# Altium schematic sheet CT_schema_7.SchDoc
size 274 x 160 mm
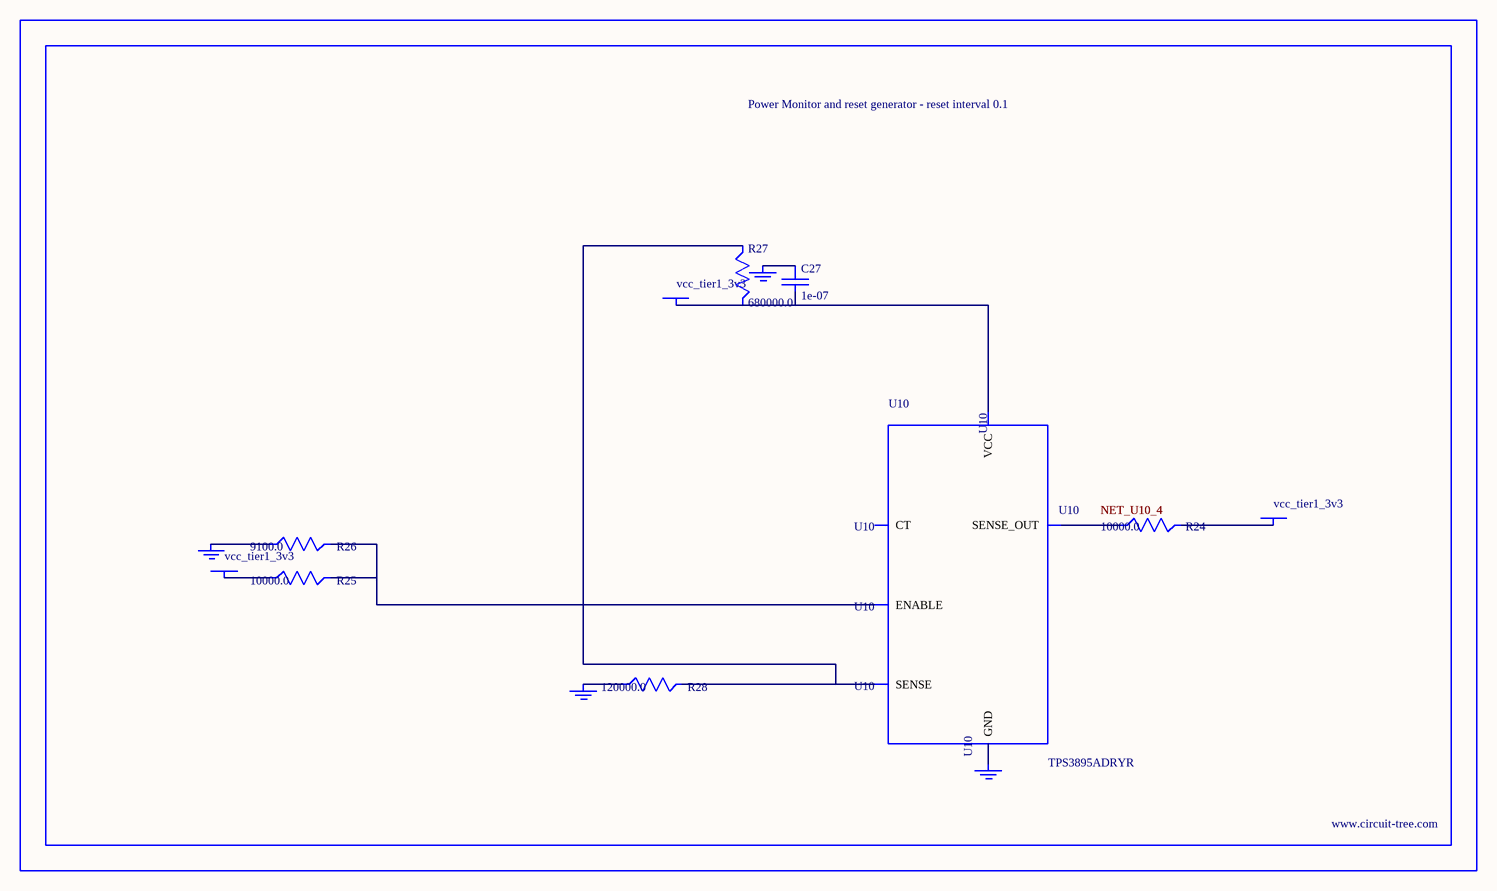
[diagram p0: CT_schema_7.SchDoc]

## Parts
BORDER6  (no value)
C27  1e-07  [C0402]
GND_INSTANCE_6_0  (no value)
GND_INSTANCE_6_1  (no value)
GND_INSTANCE_6_2  (no value)
GND_INSTANCE_6_3  (no value)
POWER_INSTANCE_6_0  vcc_tier1_3v3
POWER_INSTANCE_6_1  vcc_tier1_3v3
POWER_INSTANCE_6_2  vcc_tier1_3v3
R24  10000.0  [R0603]
R25  10000.0  [R0603]
R26  9100.0  [R0603]
R27  680000.0  [R0603]
R28  120000.0  [R0603]
U10  TPS3895ADRYR  [SON-6]

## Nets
NetC27_1: C27.1 GND_INSTANCE_6_2.0(GND)
NetC27_2: C27.2 POWER_INSTANCE_6_2.0(PWR) R27.2 U10.6(VCC)
NetGND_INSTANCE_6_0_0: GND_INSTANCE_6_0.0(GND) R26.1
NetGND_INSTANCE_6_1_0: GND_INSTANCE_6_1.0(GND) R28.1
NetGND_INSTANCE_6_3_0: GND_INSTANCE_6_3.0(GND) U10.2(GND)
NetPOWER_INSTANCE_6_0_0: POWER_INSTANCE_6_0.0(PWR) R25.1
NetPOWER_INSTANCE_6_1_0: POWER_INSTANCE_6_1.0(PWR) R24.2
NetR24_1: R24.1 U10.4(SENSE_OUT)
NetR25_2: R25.2 R26.2 U10.1(ENABLE)
NetR27_1: R27.1 R28.2 U10.3(SENSE)

Not connected (* = marked no-connect by the designer): U10 5(CT)

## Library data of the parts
BORDER6 = BORDER_PAGE6
C27 = C0402C104K3RACTU
GND_INSTANCE_6_0-GND_INSTANCE_6_3 = GND
POWER_INSTANCE_6_0-POWER_INSTANCE_6_2 = PWR
R24 R25 = RC0603JR-0710KL
R26 = RC0603JR-079K1L
R27 = RC0603JR-07680KL
R28 = RC0603JR-07120KL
